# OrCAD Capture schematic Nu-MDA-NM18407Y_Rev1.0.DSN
size A4
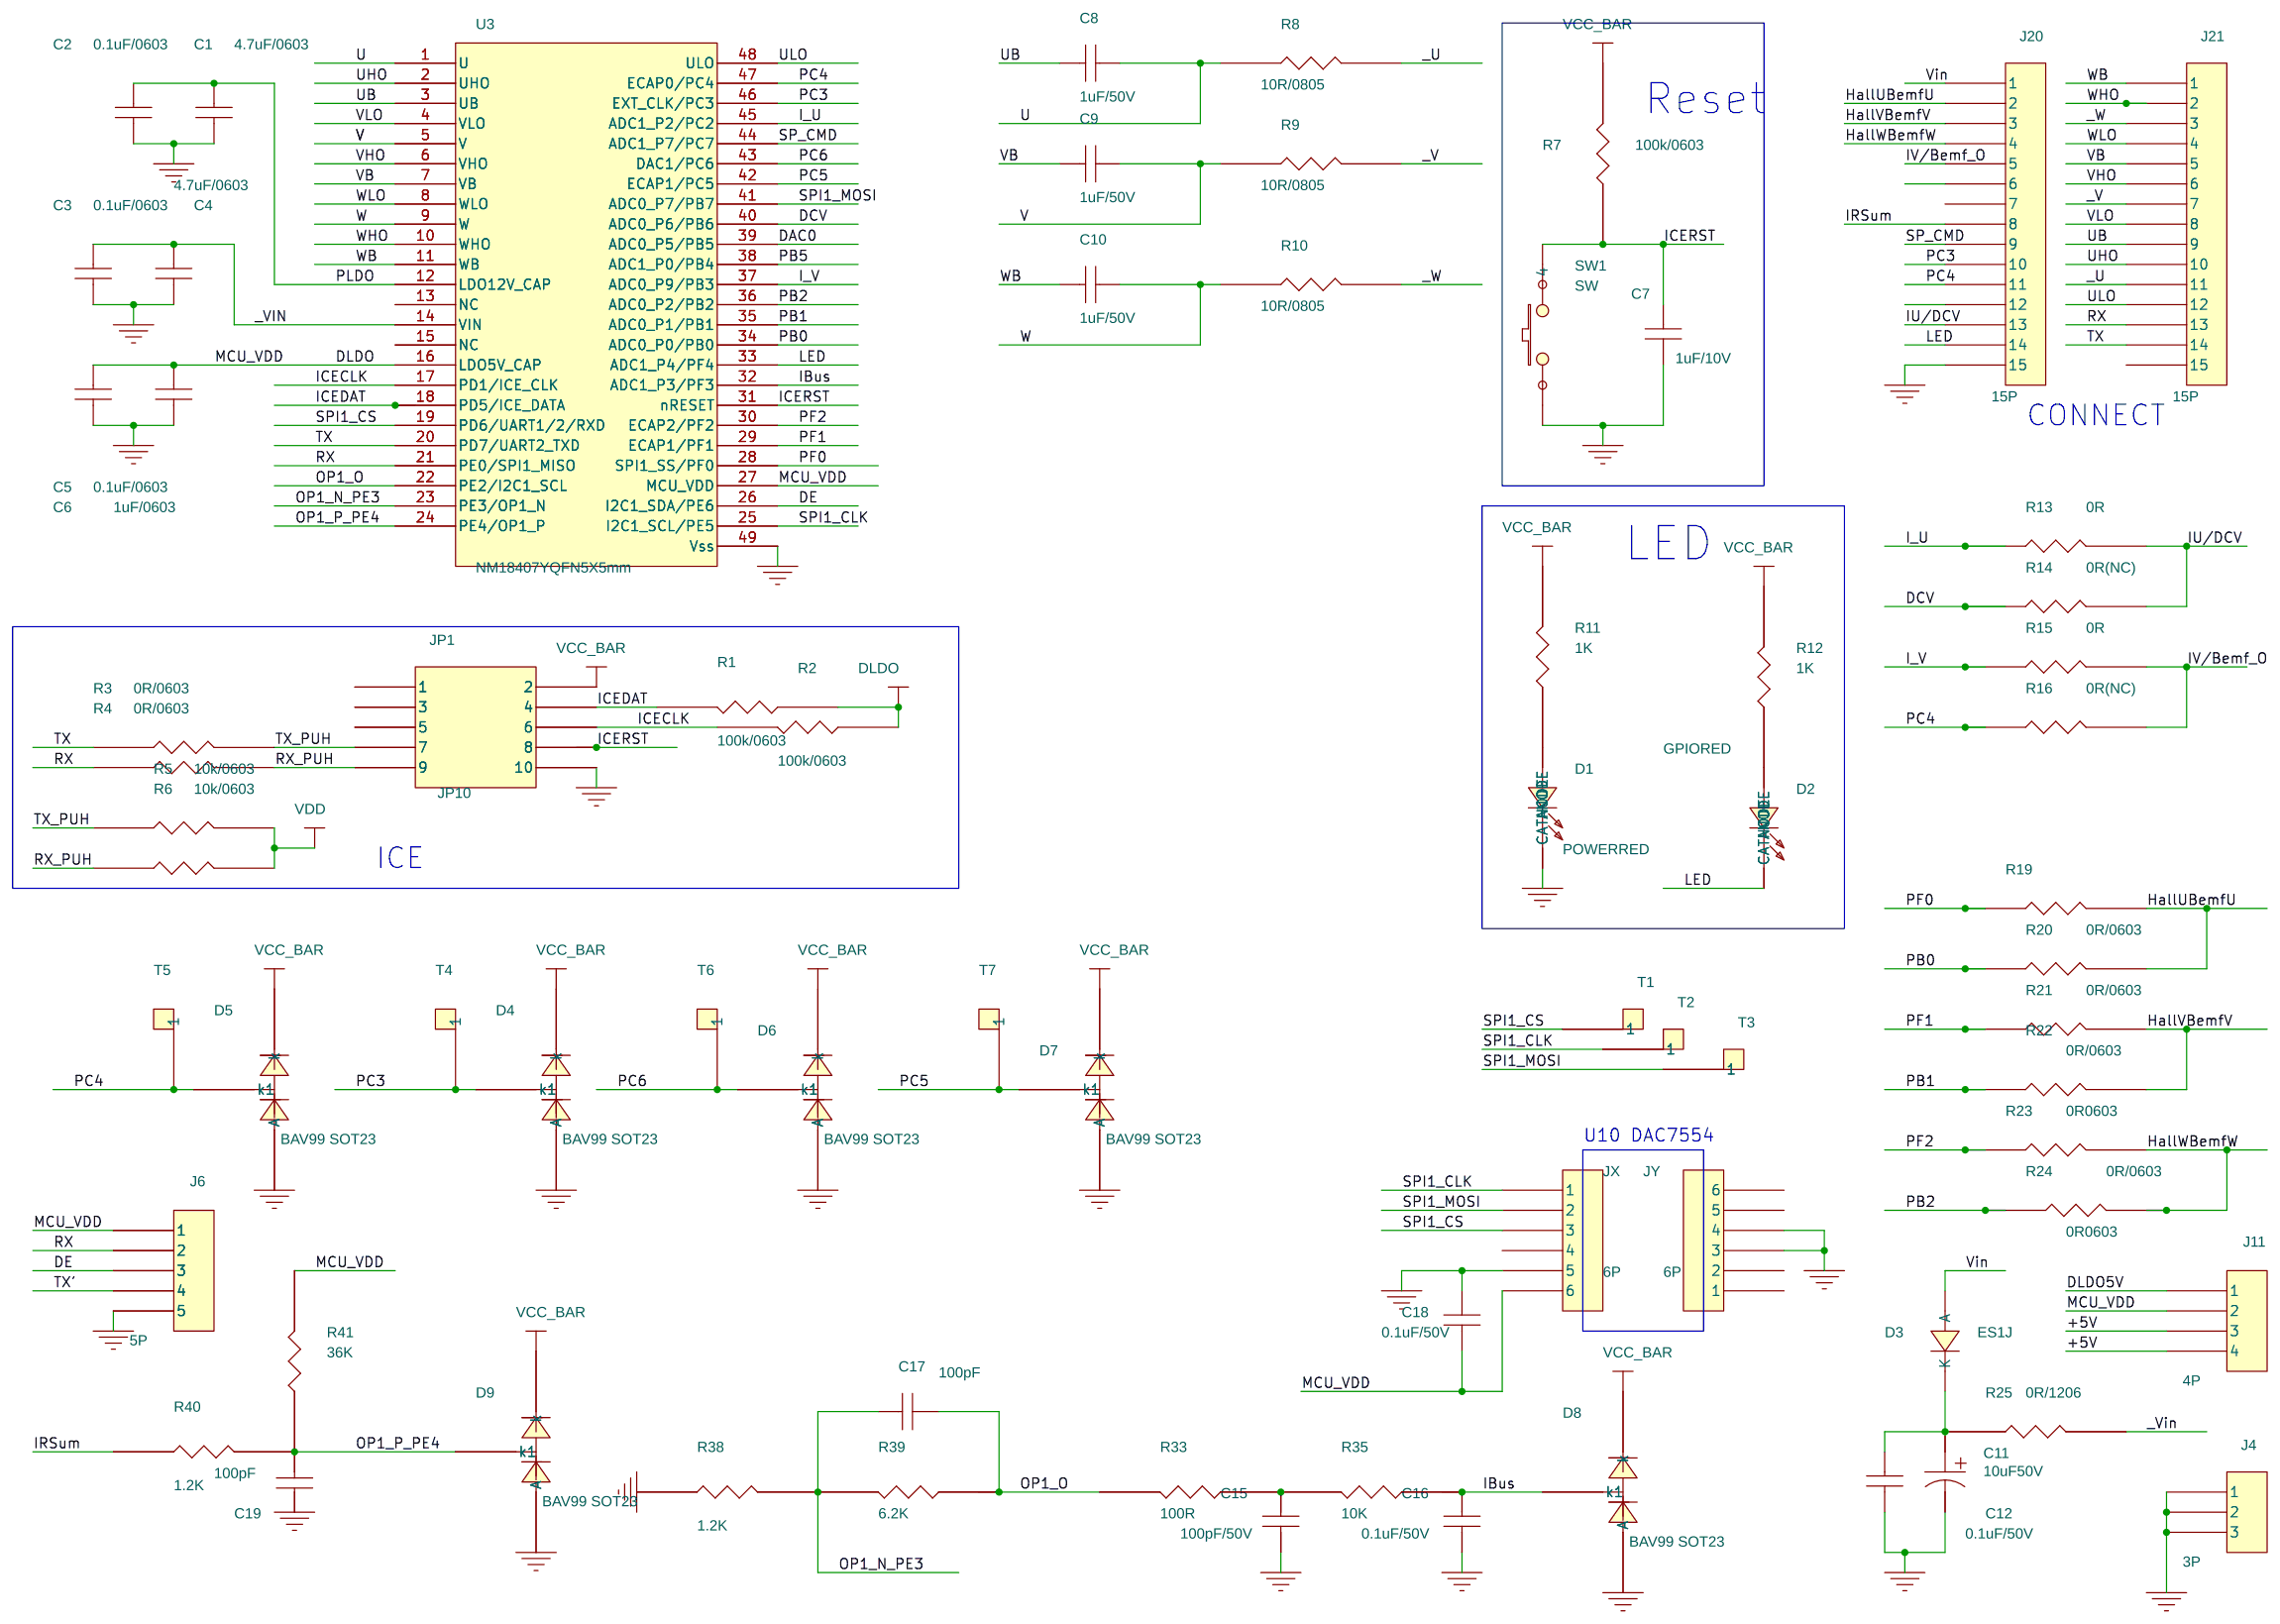
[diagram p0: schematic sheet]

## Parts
C1  4.7uF/0603
C2  0.1uF/0603
C3  0.1uF/0603
C4  4.7uF/0603
C5  0.1uF/0603
C6  1uF/0603
C7  1uF/10V
C8  1uF/50V
C9  1uF/50V
C10  1uF/50V
C11  10uF50V  [C1206]
C12  0.1uF/50V
C15  100pF/50V
C16  0.1uF/50V
C17  100pF
C18  0.1uF/50V
C19  100pF
D1  POWERRED  [LED0805]
D2  GPIORED  [LED0805]
D3  ES1J  [ES1J]
D4  BAV99 SOT23  [BAV99SOT23]
D5  BAV99 SOT23  [BAV99SOT23]
D6  BAV99 SOT23  [BAV99SOT23]
D7  BAV99 SOT23  [BAV99SOT23]
D8  BAV99 SOT23  [BAV99SOT23]
D9  BAV99 SOT23  [BAV99SOT23]
J4  3P  [HEADER3]
J6  5P  [HEADER1X5]
J11  4P  [HEADER1X4]
J20  15P  [HEADER15X1]
J21  15P  [HEADER15X1]
JP1  JP10  [HEADER5X2]
JX  6P  [HEADER1X6]
JY  6P  [HEADER1X6]
R1  100k/0603
R2  100k/0603
R3  0R/0603
R4  0R/0603
R5  10k/0603
R6  10k/0603
R7  100k/0603
R8  10R/0805
R9  10R/0805
R10  10R/0805
R11  1K  [1K/0603]
R12  1K  [1K/0603]
R13  0R  [0R/0603]
R14  0R(NC)  [0R/0603]
R15  0R  [0R/0603]
R16  0R(NC)  [0R/0603]
R19  0R/0603
R20  0R/0603
R21  0R/0603
R22  0R0603
R23  0R/0603
R24  0R0603
R25  0R/1206  [0R/1206]
R33  100R  [100R/0603]
R35  10K  [10K/0603]
R38  1.2K  [1.2K/0603]
R39  6.2K
R40  1.2K  [1.2K/0603]
R41  36K
SW1  SW  [SW_SMD_HSM]
T1  T
T2  T
T3  T
T4  T
T5  T
T6  T
T7  T
U3  NM18407YQFN5X5mm

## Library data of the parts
C1-C10 C12 C15-C19 = C1
C11 = C2
D1 D2 = LED
D3 = D
D4-D9 = BAV99_SOT23
J4 = 3P
J6 = 5P
J11 = 4P
J20 = 15P_1
J21 = 15P
JP1 = JP10
JX = 6P
JY = 6P_1
R1-R16 R19-R25 R33 R35 R38-R41 = R
SW1 = SW
T1-T7 = T
U3 = NM18407SY

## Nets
+5V: J11.3 J11.4
GND: C1.2 C2.2 C3.2 C4.2 C5.2 C6.2 C7.2 C11.2 C12.2 C15.2 C16.2 C18.1 C19.1 D1.2(CATHODE) D4.1(A) D5.1(A) D6.1(A) D7.1(A) D8.1(A) D9.1(A) J4.1 J4.2 J4.3 J6.5 J20.15 JP1.10 JX.5 JY.3 JY.4 R38.1 SW1.1 U3.49(Vss)
VDD: R5.2 R6.2
Vin: D3.2(A) J20.1
_U: J21.11 R8.2
_V: J21.7 R9.2
_VIN: C3.1 C4.1 R25.2 U3.14(VIN)
_W: J21.3 R10.2
DAC0: U3.39(ADC0_P5/PB5)
DCV: R14.1 U3.40(ADC0_P6/PB6)
DE: J6.3 U3.26(I2C1_SDA/PE6)
DLDO5V: J11.1
HallUBemfU: J20.2 R19.2 R20.2
HallVBemfV: J20.3 R21.2 R22.2
HallWBemfW: J20.4 R23.2 R24.2
I_U: R13.1 U3.45(ADC1_P2/PC2)
I_V: R15.1 U3.37(ADC0_P9/PB3)
IBus: C16.1 D8.3(k1) R35.1 U3.32(ADC1_P3/PF3)
ICECLK: JP1.6 R2.2 U3.17(PD1/ICE_CLK)
ICEDAT: JP1.4 R1.2 U3.18(PD5/ICE_DATA)
ICERST: C7.1 JP1.8 R7.1 SW1.2(4) U3.31(nRESET)
IRSum: J20.8 R40.1
IU/DCV: J20.13 R13.2 R14.2
IV/Bemf_O: J20.5 R15.2 R16.2
LED: D2.2(CATHODE) J20.14 U3.33(ADC1_P4/PF4)
MCU_VDD: C5.1 C6.1 C18.2 D4.2(k) D5.2(k) D6.2(k) D7.2(k) D8.2(k) D9.2(k) J6.1 J11.2 JP1.2 JX.6 R1.1 R2.1 R7.2 R11.2 R12.2 R41.2 U3.16(LDO5V_CAP) U3.27(MCU_VDD)
OP1_N_PE3: C17.1 R38.2 R39.2 U3.23(PE3/OP1_N)
OP1_O: C17.2 R33.2 R39.1 U3.22(PE2/I2C1_SCL)
OP1_P_PE4: C19.2 D9.3(k1) R40.2 R41.1 U3.24(PE4/OP1_P)
PB0: R20.1 U3.34(ADC0_P0/PB0)
PB1: R22.1 U3.35(ADC0_P1/PB1)
PB2: R24.1 U3.36(ADC0_P2/PB2)
PB5: U3.38(ADC1_P0/PB4)
PC3: D4.3(k1) J20.10 T4.1 U3.46(EXT_CLK/PC3)
PC4: D5.3(k1) J20.11 R16.1 T5.1 U3.47(ECAP0/PC4)
PC5: D7.3(k1) T7.1 U3.42(ECAP1/PC5)
PC6: D6.3(k1) T6.1 U3.43(DAC1/PC6)
PF0: R19.1 U3.28(SPI1_SS/PF0)
PF1: R21.1 U3.29(ECAP1/PF1)
PF2: R23.1 U3.30(ECAP2/PF2)
PLDO: C1.1 C2.1 U3.12(LDO12V_CAP)
RX: J6.2 J21.13 R4.1 U3.21(PE0/SPI1_MISO)
RX_PUH: JP1.9 R4.2 R6.1
SP_CMD: J20.9 U3.44(ADC1_P7/PC7)
SPI1_CLK: JX.1 T2.1 U3.25(I2C1_SCL/PE5)
SPI1_CS: JX.3 T1.1 U3.19(PD6/UART1/2/RXD)
SPI1_MOSI: JX.2 T3.1 U3.41(ADC0_P7/PB7)
TX: J21.14 R3.1 U3.20(PD7/UART2_TXD)
TX': J6.4
TX_PUH: JP1.7 R3.2 R5.1
U: C8.1 R8.1 U3.1(U)
UB: C8.2 J21.9 U3.3(UB)
UHO: J21.10 U3.2(UHO)
ULO: J21.12 U3.48(ULO)
V: C9.1 R9.1 U3.5(V)
VB: C9.2 J21.5 U3.7(VB)
VHO: J21.6 U3.6(VHO)
VLO: J21.8 U3.4(VLO)
W: C10.1 R10.1 U3.9(W)
WB: C10.2 J21.1 U3.11(WB)
WHO: J21.2 U3.10(WHO)
WLO: J21.4 U3.8(WLO)
N08478: C11.1 C12.1 D3.1(K) R25.1
N47350: D1.1(ANODE) R11.1
N47352: D2.1(ANODE) R12.1
N47746: C15.1 R33.1 R35.2

Not connected (* = marked no-connect by the designer): J20 6 7 12; J21 15; JP1 1 3 5; JX 4; JY 1 2 5 6; U3 13(NC) 15(NC)

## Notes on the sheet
- Reset
- CONNECT
- LED
- ICE
- U10 DAC7554
